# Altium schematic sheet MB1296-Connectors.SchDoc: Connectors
size A4; Date: 18-AUG-2016; Organization: STMicroelectronics; Address1: Microcontrollers Division; Address2: 190, avenue Célestin COQ; Address3: 13106 ROUSSET Cedex; Address4: FRANCE; DocumentNumber: MB1296; Revision: C-01; SheetNumber: 6; SheetTotal: 6; Project: STM32 LoRa Discovery
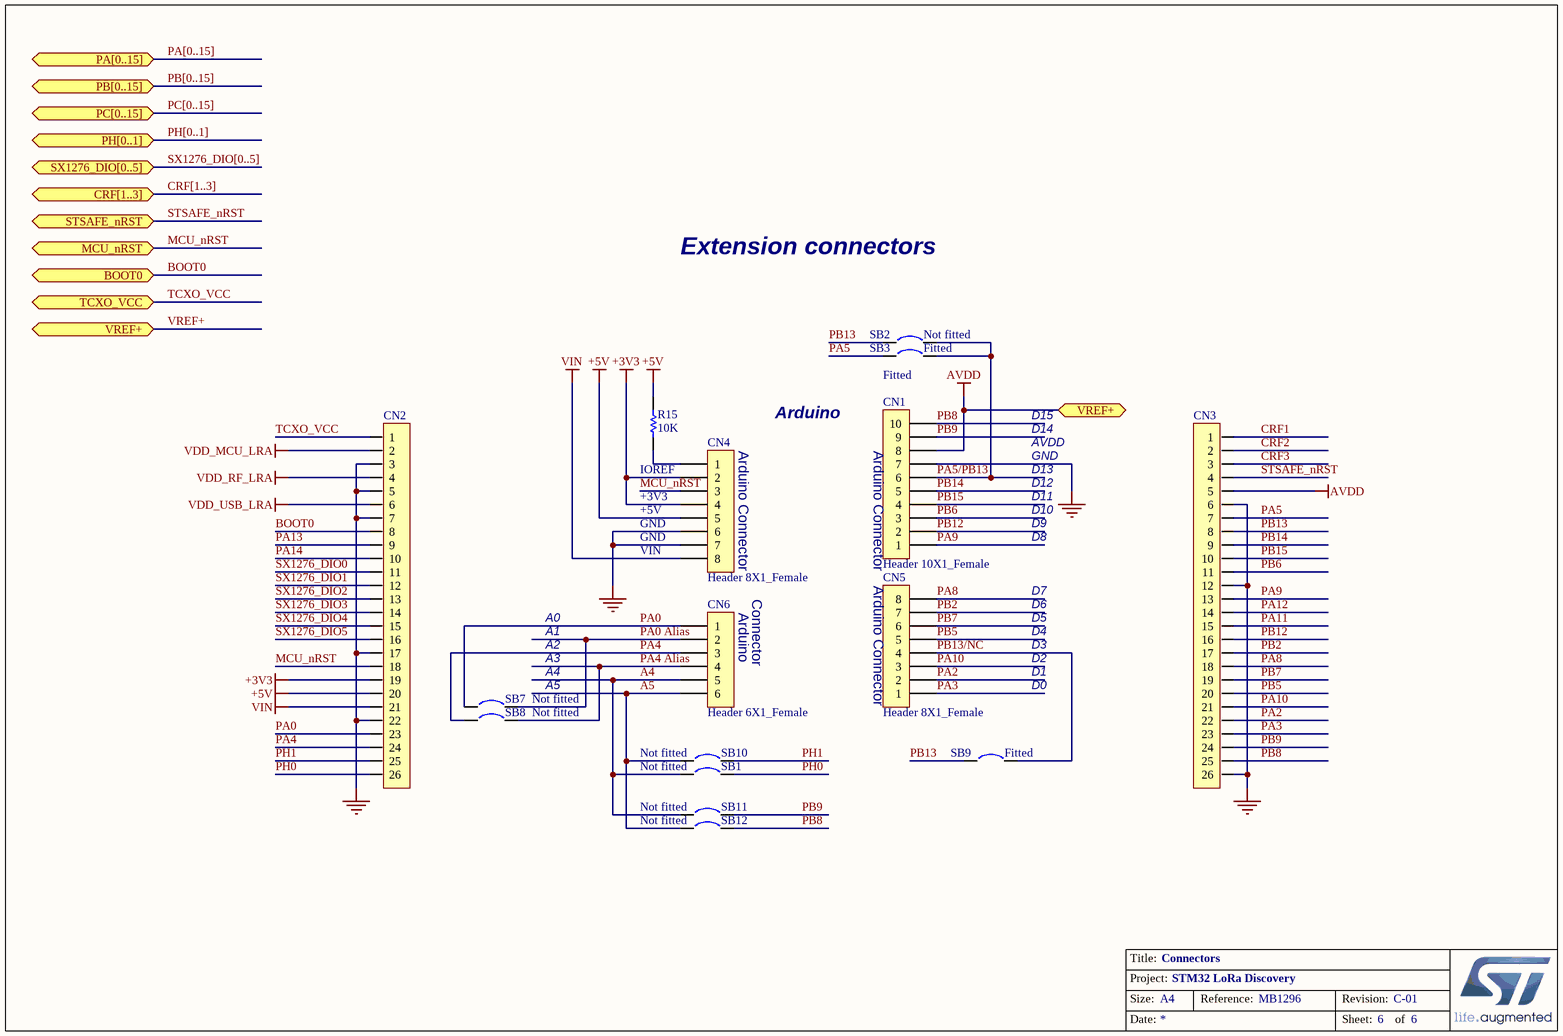
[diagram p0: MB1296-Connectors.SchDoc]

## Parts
CN1  Header 10X1_Female  [Header 1x10 Female (Wrapping)]
CN2  (no value)  [HEADER 1X26 (2.54) Male]
CN3  (no value)  [HEADER 1X26 (2.54) Male]
CN4  Header 8X1_Female  [Header 1x8Female (Wrapping)]
CN5  Header 8X1_Female  [Header 1x8Female (Wrapping)]
CN6  Header 6X1_Female  [Header 1x6 Female (Wrapping)]
R15  10K  [0603R]
SB1  Circuit Breaker  [JP2_SMD]  (value not drawn)
SB2  Circuit Breaker  [JP2_SMD]  (value not drawn)
SB3  Circuit Breaker  [JP2_SMD]  (value not drawn)
SB7  Circuit Breaker  [JP2_SMD]  (value not drawn)
SB8  Circuit Breaker  [JP2_SMD]  (value not drawn)
SB9  Circuit Breaker  [JP2_SMD]  (value not drawn)
SB10  Circuit Breaker  [JP2_SMD]  (value not drawn)
SB11  Circuit Breaker  [JP2_SMD]  (value not drawn)
SB12  Circuit Breaker  [JP2_SMD]  (value not drawn)

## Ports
BOOT0, CRF[1..3], MCU_nRST, PA[0..15] (bidir), PB[0..15] (bidir), PC[0..15] (bidir), PH[0..1] (bidir), STSAFE_nRST, SX1276_DIO[0..5] (bidir), TCXO_VCC, VREF+

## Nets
+3V3: CN2.19 CN4.2 CN4.4
+5V: CN2.20 CN4.5 R15.1
GND: CN1.7 CN2.3 CN2.5 CN2.7 CN2.17 CN2.22 CN3.6 CN3.12 CN3.26 CN4.6 CN4.7
VDD_MCU_LRA: CN2.2
VDD_RF_LRA: CN2.4
VDD_USB_LRA: CN2.6
VIN: CN2.21 CN4.8
VREF+: CN1.8 CN3.5 ; port VREF+  [also labelled AVDD]
A4: CN6.5 SB1.1 SB11.1
A5: CN6.6 SB10.1 SB12.1
BOOT0: CN2.8 ; port BOOT0
CRF1: CN3.1
CRF2: CN3.2
CRF3: CN3.3
MCU_nRST: CN2.18 CN4.3 ; port MCU_nRST
PA0: CN2.23 CN6.1 SB7.1
PA0 Alias: CN6.2 SB7.2
PA2: CN3.22 CN5.2
PA3: CN3.23 CN5.1
PA4: CN2.24 CN6.3 SB8.1
PA4 Alias: CN6.4 SB8.2
PA5: CN3.7 SB3.1
PA5/PB13: CN1.6 SB2.2 SB3.2
PA8: CN3.18 CN5.8
PA9: CN1.1 CN3.13
PA10: CN3.21 CN5.3
PA11: CN3.15
PA12: CN3.14
PA13: CN2.9
PA14: CN2.10
PB2: CN3.17 CN5.7
PB5: CN3.20 CN5.5
PB6: CN1.3 CN3.11
PB7: CN3.19 CN5.6
PB8: CN1.10 CN3.25 SB12.2
PB9: CN1.9 CN3.24 SB11.2
PB12: CN1.2 CN3.16
PB13: CN3.8 SB2.1 SB9.1
PB13/NC: CN5.4 SB9.2
PB14: CN1.5 CN3.9
PB15: CN1.4 CN3.10
PH0: CN2.26 SB1.2
PH1: CN2.25 SB10.2
STSAFE_nRST: CN3.4 ; port STSAFE_nRST
SX1276_DIO0: CN2.11
SX1276_DIO1: CN2.12
SX1276_DIO2: CN2.13
SX1276_DIO3: CN2.14
SX1276_DIO4: CN2.15
SX1276_DIO5: CN2.16
TCXO_VCC: CN2.1 ; port TCXO_VCC
NetCN4_1: CN4.1 R15.2

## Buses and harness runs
bus CRF[1..3] = port CRF[1..3]
bus PA[0..15] = port PA[0..15]
bus PB[0..15] = port PB[0..15]
bus PC[0..15] = port PC[0..15]
bus PH[0..1] = port PH[0..1]
bus SX1276_DIO[0..5] = port SX1276_DIO[0..5]

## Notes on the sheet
- Extension connectors
- (near SB3) Fitted
- (near SB2) Not fitted
- Fitted
- (near CN4) Arduino Connector
- Arduino
- Arduino Connector
- D14
- D15
- AVDD
- IOREF
- +3V3
- +5V
- D10
- D13
- D12
- D11
- GND
- (near CN4) GND
- (near CN4) VIN
- (near CN5) Arduino Connector
- D8
- D9
- A0
- A1
- A2
- (near CN6) Arduino
- Connector
- D4
- D3
- D5
- D6
- D7
- Not fitted
- A3
- A4
- A5
- D0
- D1
- D2
- (near SB10) Not fitted
- (near SB9) Fitted
- (near SB11) Not fitted

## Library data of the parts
CN1 = Header 10X1_Female: Header, 10-Pin, Single row,female; Manufacturer: Lyconn; Manufacturer P/N: 218110S1610; Provided by: Subcon
CN2 CN3 = CON_SLW-126-01-T-S: Connector header 26x1 2.54mm female; Manufacturer: Samtec; Manufacturer P/N: MTSW-126-22-T-S-265; Fitted: Yes
CN4 CN5 = Header 8X1_Female: Header, 8-Pin, Single row,female; Manufacturer: Lyconn; Manufacturer P/N: 218108S1610; Provided by: Subcon
CN6 = Header 6X1_Female: Header, 6-Pin, Single row,female; Manufacturer: Lyconn; Manufacturer P/N: 218106S1610; Provided by: Subcon
R15 = Resistor_ST: Resistor 0603; Manufacturer: YAGEO; Manufacturer P/N: RC0603JR-0710KL; Provided by: Subcon
SB1 SB2 SB7 SB8 SB10-SB12 = Circuit Breaker: Fitted: No
SB3 SB9 = Circuit Breaker: Fitted: Yes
